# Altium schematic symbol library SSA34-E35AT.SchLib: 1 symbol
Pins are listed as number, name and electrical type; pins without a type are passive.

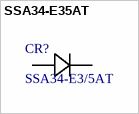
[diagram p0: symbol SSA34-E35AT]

## SSA34-E35AT
designator CR?, comment SSA34-E3/5AT
3A,40V,SMA SKY RECT; Manufacturer_Name: Vishay
footprint CR_A34-E35AT_VIS
pins: 1, 2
